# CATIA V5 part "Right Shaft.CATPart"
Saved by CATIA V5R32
Part number: Right hand shaft
Bounding box of the stored display mesh (mm): x 0 to 100, y -35 to 35, z -35 to 35
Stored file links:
  D:\PROJECTS\Project 2022\CATIA V5 6R 2022\Resources\Part Files\c16_catia_v5_6r2022_prt\Universal Joint-(Fig16-49)\Right Shaft.CATPart
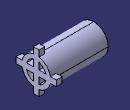
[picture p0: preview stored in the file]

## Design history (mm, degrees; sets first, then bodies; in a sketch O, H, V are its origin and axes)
Body1 (main body)
  Sketch1 on yz-plane, origin (0, 0, 0), H (0, 1, 0), V (0, 0, 1)
    circle A1 centre (0, 0) radius 25
    circle A2 centre (0, 0) radius 17.5
    radius A1 = 25
    radius A2 = 17.5
  Pad1: profile Sketch1, direction (1, 0, 0), length 100
  Sketch2 on end face of Pad1, origin (100, 0, 0), H (0, 1, 0), V (0, 0, 1)
    line L1 (5, 35) -> (5, -35)
    line L2 (5, -35) -> (-5, -35)
    line L3 (-5, -35) -> (-5, 35)
    line L4 (-5, 35) -> (5, 35)
    length L1 = 70
    length L4 = 10
    vertical: L1 V, L3 V
    horizontal: L2 H, L4 H
    equidistance: L1 L3 O, L2 L4 O
  Pad2: profile Sketch2, direction (-1, 0, 0), length 10
  CircPattern1: of the body so far, instances 2, angular step 90, axis from face of Pad1 from Sketch1.A1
